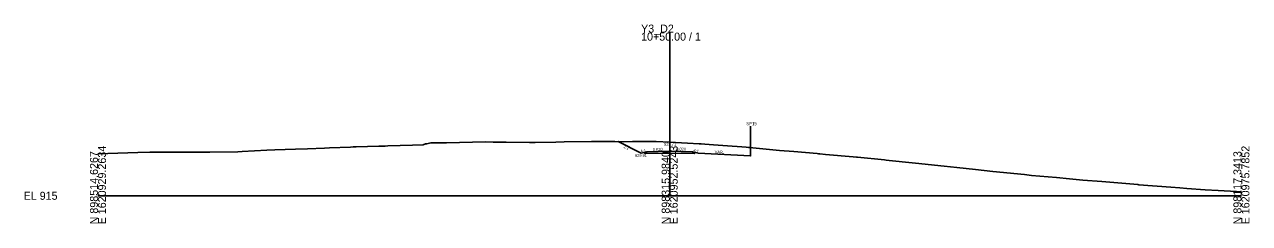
# Model space of a CAD drawing. Extents: x 162 to 3869, y 3 to 5514.
# Drawn here: x 3440.3 to 3868.9, y 1869.4 to 1939 of the extents above; entities that cross this region are included whole.
import ezdxf

# ---------------------------------------------------------------- set-up
doc = ezdxf.new("R2010")
doc.units = 0
for name, color, linetype in [('Exist Cross Section Cell', 7, 'Continuous'), ('Exist XS Center Line Elevation Label', 7, 'Continuous'), ('Exist XS Ground Line', 7, 'Continuous'), ('Old_Level_1', 7, 'Continuous'), ('Prop CMT Pvmt Gravel', 7, 'Continuous'), ('Prop CMT Slope Grass', 7, 'Continuous'), ('Prop CMT Subgrade Earthwork', 7, 'Continuous'), ('Prop XS Earthwork Shape', 7, 'Continuous'), ('Prop XS SE Text', 7, 'Continuous'), ('Prop XS Shear Point Element', 7, 'Continuous'), ('Prop XS Side Slope Text', 7, 'Continuous')]:
    doc.layers.add(name, color=color, linetype=linetype)

msp = doc.modelspace()

# ---------------------------------------------------------------- linework, layer by layer
at = {"layer": 'Exist Cross Section Cell'}
for p, q in [((3666.03, 1879.08), (3666.03, 1936.13)), ((3466.03, 1879.08), (3666.03, 1879.08)), ((3666.03, 1879.08), (3866.03, 1879.08))]:
    msp.add_line(p, q, dxfattribs=at)
at = {"layer": 'Exist XS Ground Line'}
msp.add_lwpolyline([(3466.03, 1893.79), (3480.02, 1894.16), (3484.17, 1894.27), (3484.94, 1894.27), (3486.4, 1894.3), (3495, 1894.34), (3495.6, 1894.35), (3503.36, 1894.36), (3505.12, 1894.36), (3514.98, 1894.42), (3516.52, 1894.53), (3525.05, 1895.02), (3527.93, 1895.11), (3535.12, 1895.32), (3539.33, 1895.46), (3545.29, 1895.72), (3546.98, 1895.8), (3554.32, 1896.09), (3555.29, 1896.17), (3556.38, 1896.24), (3564.23, 1896.37), (3564.99, 1896.39), (3566.45, 1896.48), (3567.46, 1896.51), (3576.07, 1896.76), (3579.81, 1896.86), (3580.58, 1897.19), (3581.06, 1897.29), (3582.5, 1897.58), (3583.84, 1897.57), (3584.25, 1897.58), (3585.52, 1897.6), (3587.93, 1897.64), (3601.64, 1897.89), (3604.33, 1897.79), (3608.79, 1897.8), (3617.02, 1897.72), (3619, 1897.7), (3626.2, 1897.86), (3629.1, 1897.91), (3638.7, 1898.03), (3646.89, 1898.03), (3650.02, 1897.99), (3653.01, 1898.05), (3655.83, 1898.08), (3656.38, 1898.09), (3660.98, 1898.04), (3661.34, 1898.04), (3666.03, 1897.79), (3670.17, 1897.56), (3672.28, 1897.42), (3676.36, 1897.27), (3677.04, 1897.2), (3678.29, 1897.1), (3681.33, 1896.85), (3684.6, 1896.65), (3686.24, 1896.54), (3691.32, 1896.16), (3692.81, 1896.03), (3704.4, 1894.96), (3709.52, 1894.54), (3717.67, 1893.81), (3718.07, 1893.78), (3718.58, 1893.75), (3720.52, 1893.56), (3730.2, 1892.68), (3731.34, 1892.56), (3731.68, 1892.53), (3741.19, 1891.59), (3741.72, 1891.54), (3742.84, 1891.43), (3750.8, 1890.56), (3752.02, 1890.43), (3762.07, 1889.39), (3766.45, 1888.91), (3772.96, 1888.27), (3779.06, 1887.59), (3790.15, 1886.46), (3792.59, 1886.22), (3801.39, 1885.42), (3805.9, 1885), (3810.57, 1884.59), (3817.25, 1884.02), (3829.83, 1882.99), (3830.15, 1882.96), (3841.37, 1882.06), (3844.46, 1881.81), (3846.95, 1881.57), (3853.31, 1881.14), (3857.89, 1880.9), (3864.32, 1880.55), (3866.03, 1880.4)], dxfattribs=at)
at = {"layer": 'Old_Level_1'}
for p, q in [((3656.94, 1894.22), (3658.03, 1894.49)), ((3675.11, 1894.22), (3674.03, 1894.49))]:
    msp.add_line(p, q, dxfattribs=at)
at = {"layer": 'Prop CMT Pvmt Gravel'}
for points in [[(3658.03, 1894.49), (3657.34, 1893.81)], [(3666.03, 1894.65), (3658.03, 1894.49)], [(3666.03, 1894.65), (3674.03, 1894.49)], [(3674.03, 1894.49), (3674.71, 1893.81)]]:
    msp.add_lwpolyline(points, dxfattribs=at)
at = {"layer": 'Prop CMT Slope Grass'}
for p, q in [((3647.98, 1898.02), (3656.03, 1893.99)), ((3656.03, 1893.99), (3656.94, 1894.22)), ((3676.03, 1893.99), (3675.11, 1894.22)), ((3694.32, 1893.02), (3694.32, 1895.89)), ((3694.32, 1893.02), (3676.03, 1893.99))]:
    msp.add_line(p, q, dxfattribs=at)
at = {"layer": 'Prop CMT Subgrade Earthwork'}
for p, q in [((3656.94, 1894.22), (3657.34, 1893.81)), ((3675.11, 1894.22), (3674.71, 1893.81)), ((3666.03, 1893.98), (3657.34, 1893.81)), ((3666.03, 1893.98), (3674.71, 1893.81))]:
    msp.add_line(p, q, dxfattribs=at)
at = {"layer": 'Prop XS Earthwork Shape'}
for points in [[(3677.04, 1897.2), (3678.29, 1897.1), (3681.33, 1896.85), (3684.6, 1896.65), (3686.24, 1896.54), (3691.32, 1896.16), (3692.81, 1896.03), (3694.32, 1895.89), (3694.32, 1893.02), (3676.03, 1893.99), (3675.11, 1894.22), (3674.71, 1893.81), (3666.03, 1893.98), (3657.34, 1893.81), (3656.94, 1894.22), (3656.03, 1893.99), (3647.98, 1898.02), (3650.02, 1897.99), (3653.01, 1898.05), (3655.83, 1898.08), (3656.38, 1898.09), (3660.98, 1898.04), (3661.34, 1898.04), (3666.03, 1897.79), (3670.17, 1897.56), (3672.28, 1897.42), (3676.36, 1897.27)], [(3670.17, 1897.56), (3672.28, 1897.42), (3676.36, 1897.27), (3677.04, 1897.2), (3678.29, 1897.1), (3681.33, 1896.85), (3684.6, 1896.65), (3686.24, 1896.54), (3691.32, 1896.16), (3692.81, 1896.03), (3694.32, 1895.89), (3694.32, 1893.02), (3676.03, 1893.99), (3675.11, 1894.22), (3674.71, 1893.81), (3666.03, 1893.98), (3657.34, 1893.81), (3656.94, 1894.22), (3656.03, 1893.99), (3647.98, 1898.02), (3650.02, 1897.99), (3653.01, 1898.05), (3655.83, 1898.08), (3656.38, 1898.09), (3660.98, 1898.04), (3661.34, 1898.04), (3666.03, 1897.79)]]:
    msp.add_lwpolyline(points, close=True, dxfattribs=at)
at = {"layer": 'Prop XS Shear Point Element'}
msp.add_line((3694.32, 1903.42), (3694.32, 1895.89), dxfattribs=at)

# ---------------------------------------------------------------- texts
at = {"layer": 'Exist Cross Section Cell'}
for s, p in [('Y3_D2', (3656.03, 1936.13)), ('10+50.00 / 1', (3656.03, 1933.33)), ('EL 915', (3440.03, 1877.68))]:
    msp.add_text(s, height=2.8, dxfattribs=at).set_placement(p)
for s, p in [('N 898514.6267', (3466.03, 1869.08)), ('E 1620929.2634', (3468.83, 1869.08)), ('N 898315.9840', (3666.03, 1869.08)), ('E 1620952.5243', (3668.83, 1869.08)), ('N 898117.3413', (3866.03, 1869.08)), ('E 1620975.7852', (3868.83, 1869.08))]:
    msp.add_text(s, height=2.8, rotation=90, dxfattribs=at).set_placement(p)
at = {"layer": 'Exist XS Center Line Elevation Label'}
msp.add_text('933.71', height=1, dxfattribs=at).set_placement((3664.06, 1896.59))
at = {"layer": 'Prop XS SE Text'}
for rotation, p in [(1.1458, (3660.1, 1894.78)), (358.8542, (3668.31, 1894.93))]:
    msp.add_text('0.020', height=1, rotation=rotation, dxfattribs=at).set_placement(p)
at = {"layer": 'Prop XS Shear Point Element'}
msp.add_text('SP15', height=1.084, rotation=360, dxfattribs=at).set_placement((3692.85, 1903.74))
at = {"layer": 'Prop XS Side Slope Text'}
for s, rotation, p in [('2:1', 333.4349, (3649.8, 1895.92)), ('4:1', 14.7964, (3655.99, 1894.11)), ('4:1', 345.2036, (3674.24, 1894.59)), ('VAR.', 358.7469, (3681.76, 1893.89))]:
    msp.add_text(s, height=1, rotation=rotation, dxfattribs=at).set_placement(p)
msp.add_text('929.91', height=1, dxfattribs=at).set_placement((3653.87, 1892.65))

doc.saveas('drawing.dxf')
